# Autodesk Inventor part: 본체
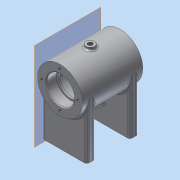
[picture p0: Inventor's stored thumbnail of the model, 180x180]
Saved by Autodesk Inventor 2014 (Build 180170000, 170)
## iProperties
Created: 2020-07
Part Number: 본체
Material: Aluminum 6061
Document SubType Name: Modeling
Designer: kh
Density: 2.71 g/cm^3
Appearance: Aluminum - Flat
Mass: 306.438 g
Surface Area: 357.696 cm^2
Volume: 113.077 cm^3
Author: kh
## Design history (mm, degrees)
sketch "Sketch1"
  geometry: C1 r 26 at (0, 0); 1 further point
  constraints: 1 centre point, 1 coincident
  dimensions: "d0" = 26 radius of C1
extrude "Extrusion1" new body sketch "Sketch1" stored distance "d1" = 70; taper "d2" = 0 deg
workplane "Work Plane1"
sketch "Sketch2"
  geometry: L1 (26, 0)-(26, -64); L2 (26, -64)-(-26, -64); L3 (-26, -64)-(-26, 0); A1 r 26 centre (0, 0) between (26, 0) and (-26, 0) reference; 1 further point
  constraints: 6 end point, 2 point on circle, 2 tangent, 1 perpendicular, 1 vertical
  dimensions: "d4" = 64 distance of L1.start L1.end; "d5" = 52 distance of L1.end L2.end
extrude "Extrusion2" join sketch "Sketch2" distance "d6" = 10; taper "d7" = 0 deg
mirror "Mirror1"
sketch "Sketch3"
  geometry: L1 (26, -35)-(26, 35) reference; L2 (0, 20)-(-64, 20) reference; L3 (0, -20)-(-64, -20) reference; L4 (0, -20)-(-64, -20) reference; L5 (0, -30)-(0, -20) reference; L6 (0, -30)-(-64, -30) reference; L7 (-64, -20)-(-64, -30) reference; L8 (0, 20)-(-64, 20) reference; L9 (-64, 20)-(-64, 30) reference; L10 (0, 30)-(-64, 30) reference; L11 (0, 20)-(0, 30) reference; L12 (0, -30)-(0, -20) reference; L13 (0, -20)-(0, -20) reference; L14 (0, -30)-(0, -20) reference; L15 (0, -30)-(0, -30) reference; L16 (0, 20)-(0, 30) reference; L17 (0, 30)-(0, 30) reference; L18 (0, 20)-(0, 30) reference; L19 (0, 20)-(0, 20) reference; L20 (-26, -35)-(26, -35) reference; L21 (26, 35)-(-26, 35) reference; L22 (-64, 20)-(-64, 30) reference; L23 (0, 35)-(0, -35); L24 (0, 35)-(16, 35); L25 (16, 35)-(16, 23); L26 (16, 23)-(14, 23); L27 (14, 23)-(14, 21); L28 (14, 21)-(21, 21); L29 (21, 21)-(21, -21); L30 (21, -21)-(14, -21); L31 (14, -21)-(14, -23); L32 (14, -23)-(16, -23); L33 (16, -23)-(16, -35); L34 (16, -35)-(0, -35); 1 further point
  constraints: 24 end point, 6 parallel, 3 perpendicular, 2 midpoint, 2 point on line, 1 collinear
  dimensions: "d8" = 12 distance of L25.end L24.end; "d9" = 12 distance of L33.end L32.end; "d10" = 2 distance of L27.end L26.end; "d11" = 42 distance of L29.end L28.end; "d12" = 42 diameter of L29 L23; "d13" = 28 diameter of L31 L23; "d14" = 28 diameter of L27 L23; "d15" = 32 diameter of L25 L23; "d16" = 32 diameter of L33 L23
revolve "Revolution1" sketch "Sketch3" stored, may be unused: angle "d17" = 90 deg
sketch "Sketch4"
  geometry: L1 (26, -64)-(26, 0) reference; L2 (-26, 0)-(-26, -64) reference; L3 (-26, -64)-(26, -64) reference; L4 (26, -64)-(26, 0) reference; L5 (0, 0)-(0, -26); L6 (8.241, -22.643)-(10, -27.475); L7 (15.638, -25.423)-(13.88, -20.591); L8 (10, -27.475)-(15.638, -25.423); L9 (8.241, -22.643)-(13.88, -20.591); L10 (0, 0)-(8.241, -22.643); A1 r 26 centre (0, 0) between (-26, 0) and (26, 0) reference; A2 r 26 centre (0, 0) between (-26, 0) and (26, 0) reference; 1 further point
  constraints: 12 end point, 3 perpendicular, 1 point on circle
  dimensions: "d21" = 6 distance between parallel lines of L7 L6; "d89" = 20 deg angle of L6 L5
revolve "Revolution2" sketch "Sketch4" stored, may be unused: angle "d22" = 90 deg
workplane "Work Plane2"
sketch "Sketch5"
  geometry: C1 r 5 at (0, 0); 1 further point
  constraints: 1 centre point, 1 coincident
  dimensions: "d24" = 5 radius of C1
extrude "Extrusion3" join sketch "Sketch5" distance "d25" = 6.25; taper "d26" = 0 deg
sketch "Sketch6"
  geometry: L1 (0, -10)-(52, -10) reference; L2 (52, 0)-(52, -10) reference; L3 (26, 20)-(26, -15.02); 2 further points
  constraints: 2 end point, 1 parallel
  dimensions: "d27" = 20 distance from line of L3 point (6, -5); "d28" = 20 distance from line of L3 point (46, -5); "d29" = 5 distance from line of point (46, -5) L1; "d30" = 5 distance from line of point (6, -5) L1
hole "Hole1" sketch "Sketch6" at (46, -5), (6, -5) diameter "d31" = 4.134; stored, may be unused: countersink angle "d35" = 90 deg, drill point angle "d37" = 118 deg; dims "d32" = 8, "d33" = 4, "d34" = 2, "d36" = 10
mirror "Mirror2"
hole "Hole2" diameter "d40" = 5.188; stored, may be unused: countersink angle "d44" = 90 deg, drill point angle "d46" = 118 deg; dims "d38" = 10, "d39" = 10, "d41" = 8, "d42" = 4, "d43" = 2, "d45" = 16.25
hole "Hole3" diameter "d49" = 5.188; stored, may be unused: countersink angle "d53" = 90 deg, drill point angle "d55" = 118 deg; dims "d50" = 6, "d51" = 4, "d52" = 2, "d54" = 16.25, "d81" = 10, "d82" = 10
sketch "Sketch7" dims "d56" = 21
  geometry: C1 r 26 at (0, 0) reference; 2 further points
  constraints: 1 coincident, 1 horizontal alignment, 2 other
hole "Hole4" sketch "Sketch7" at (-21, 0) diameter "d57" = 3.242; stored, may be unused: countersink angle "d61" = 90 deg, drill point angle "d63" = 118 deg; dims "d58" = 8, "d59" = 4, "d60" = 2, "d62" = 10
pattern_circular "Circular Pattern1" dims angle "d65" = 360 deg
mirror "Mirror3"
workplane "Work Plane3"
fillet "Fillet1" dims "d72" = 2
chamfer "Chamfer1" distance "d73" = 1; stored, may be unused: second distance "d74" = 2, angle "d75" = 45 deg
fillet "Fillet3" dims "d77" = 3
fillet "Fillet4" dims "d78" = 3
fillet "Fillet5" dims "d79" = 0.3
fillet "Fillet6" dims "d80" = 3
workplane "Work Plane5"
sketch "Sketch11"
  geometry: L1 (-26, -35)-(-26, 35) reference; L2 (16, -34)-(-16, -34) reference; L3 (-26, -35)-(26, -35) reference; 2 further points
  constraints: 1 other
  dimensions: "d91" = 35 distance from line of point (0, 0) L3; "d92" = 26 distance from line of point (0, 0) L1
emboss "Emboss3" sketch "Sketch11" dims "d93" = 0.5, "d94" = 0
body "Solid1"
node "Projected Loop1"
node "Projected Loop2"
node "Projected Loop3"
node "Projected Loop4"
other parameters: "d23" = 29, "d67" = 26, "d90" = -26
